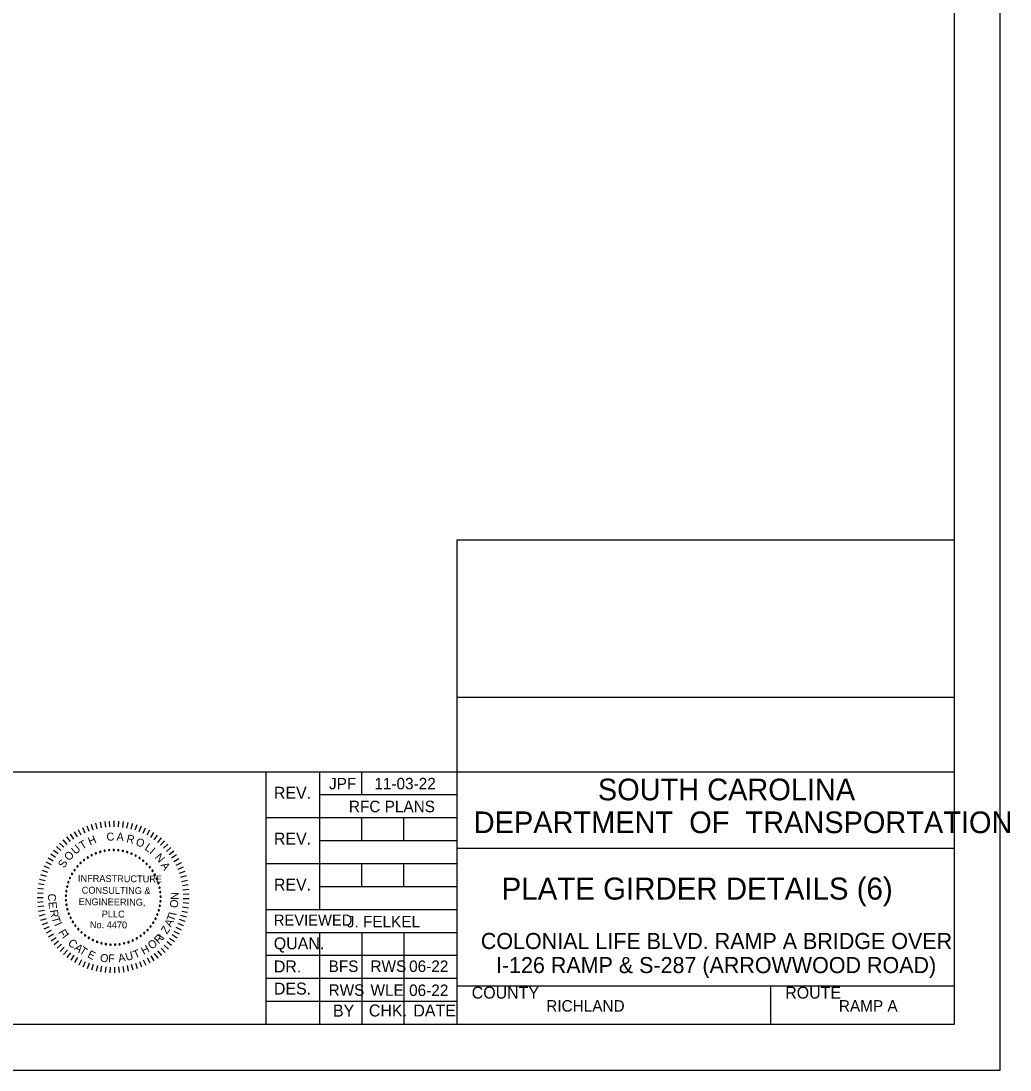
# Model space of a CAD drawing. Extents: x -383 to -161, y -356 to -94.
# Drawn here: x -203.87 to -160.75, y -187.49 to -141.77 of the extents above; entities that cross this region are included whole.
import ezdxf

# ---------------------------------------------------------------- set-up
doc = ezdxf.new("R2010")
doc.units = 0
for name, color, linetype in [('BR_BORDER LINES', 7, 'Continuous'), ('BR_TEXT', 7, 'Continuous'), ('Level 31', 7, 'Continuous')]:
    doc.layers.add(name, color=color, linetype=linetype)

msp = doc.modelspace()

# ---------------------------------------------------------------- linework, layer by layer
at = {"layer": 'BR_BORDER LINES'}
for p, q in [((-163.178, -185.489), (-163.178, -101.489)), ((-184.846, -185.489), (-184.846, -164.383)), ((-184.846, -164.383), (-163.178, -164.383)), ((-184.845, -171.242), (-163.178, -171.242)), ((-214.64, -174.489), (-193.18, -174.489)), ((-193.18, -185.489), (-193.18, -174.489)), ((-193.18, -174.489), (-163.178, -174.489)), ((-190.846, -174.489), (-190.846, -180.489)), ((-189.013, -175.489), (-189.013, -174.489)), ((-190.846, -175.489), (-184.846, -175.489)), ((-193.18, -176.489), (-184.846, -176.489)), ((-189.013, -177.489), (-189.013, -176.489)), ((-187.179, -177.489), (-187.179, -176.489)), ((-190.846, -177.489), (-184.846, -177.489)), ((-184.846, -177.822), (-184.846, -177.822)), ((-184.846, -177.823), (-163.178, -177.823)), ((-193.18, -178.489), (-184.846, -178.489)), ((-189.013, -179.489), (-189.013, -178.489)), ((-187.179, -179.489), (-187.179, -178.489)), ((-190.846, -179.489), (-184.846, -179.489)), ((-193.18, -180.489), (-184.846, -180.489)), ((-193.18, -181.489), (-184.846, -181.489)), ((-190.846, -181.489), (-190.846, -185.489)), ((-189.013, -181.489), (-189.013, -185.489)), ((-187.179, -181.489), (-187.179, -185.489)), ((-193.18, -182.489), (-184.846, -182.489)), ((-193.18, -183.489), (-184.846, -183.489)), ((-184.846, -183.823), (-163.178, -183.823)), ((-184.456, -183.823), (-163.178, -183.823)), ((-171.179, -185.489), (-171.179, -183.823)), ((-193.18, -184.489), (-184.846, -184.489)), ((-297.843, -185.489), (-163.178, -185.489))]:
    msp.add_line(p, q, dxfattribs=at)
at = {"layer": 'BR_TEXT'}
for p, q in [((-201.188, -176.92), (-201.084, -177.153)), ((-201.001, -176.844), (-200.912, -177.082)), ((-200.81, -176.779), (-200.735, -177.023)), ((-200.615, -176.726), (-200.555, -176.974)), ((-200.417, -176.685), (-200.373, -176.936)), ((-200.217, -176.656), (-200.188, -176.909)), ((-200.016, -176.64), (-200.002, -176.894)), ((-199.814, -176.636), (-199.816, -176.89)), ((-199.612, -176.644), (-199.63, -176.898)), ((-199.411, -176.664), (-199.444, -176.917)), ((-199.212, -176.697), (-199.26, -176.947)), ((-199.015, -176.741), (-199.079, -176.988)), ((-198.821, -176.798), (-198.9, -177.04)), ((-198.631, -176.866), (-198.724, -177.103)), ((-201.879, -177.334), (-201.723, -177.535)), ((-201.716, -177.215), (-201.572, -177.425)), ((-201.546, -177.106), (-201.415, -177.324)), ((-201.37, -177.007), (-201.252, -177.233)), ((-198.446, -176.946), (-198.553, -177.177)), ((-198.265, -177.037), (-198.387, -177.261)), ((-198.091, -177.139), (-198.226, -177.355)), ((-197.923, -177.251), (-198.071, -177.458)), ((-197.762, -177.373), (-197.922, -177.571)), ((-202.321, -177.748), (-202.13, -177.917)), ((-202.182, -177.601), (-202.002, -177.781)), ((-202.035, -177.463), (-201.866, -177.654)), ((-197.609, -177.505), (-197.781, -177.693)), ((-197.464, -177.646), (-197.647, -177.823)), ((-197.329, -177.795), (-197.522, -177.961)), ((-202.679, -178.235), (-202.461, -178.366)), ((-202.57, -178.065), (-202.36, -178.21)), ((-202.45, -177.903), (-202.25, -178.06)), ((-197.202, -177.952), (-197.405, -178.106)), ((-197.086, -178.117), (-197.298, -178.258)), ((-196.979, -178.289), (-197.199, -178.417)), ((-202.867, -178.593), (-202.634, -178.696)), ((-202.779, -178.411), (-202.553, -178.529)), ((-196.883, -178.467), (-197.111, -178.581)), ((-196.799, -178.65), (-197.033, -178.75)), ((-203.063, -179.165), (-202.815, -179.225)), ((-203.009, -178.97), (-202.766, -179.045)), ((-202.944, -178.779), (-202.705, -178.869)), ((-196.725, -178.838), (-196.965, -178.924)), ((-196.664, -179.03), (-196.908, -179.101)), ((-203.134, -179.562), (-202.881, -179.592)), ((-203.104, -179.363), (-202.853, -179.407)), ((-196.614, -179.226), (-196.862, -179.282)), ((-196.576, -179.424), (-196.827, -179.465)), ((-196.55, -179.625), (-196.804, -179.65)), ((-203.156, -179.965), (-202.901, -179.964)), ((-203.151, -179.764), (-202.897, -179.777)), ((-196.537, -179.826), (-196.791, -179.836)), ((-196.535, -180.028), (-196.79, -180.022)), ((-203.149, -180.167), (-202.895, -180.15)), ((-203.129, -180.368), (-202.877, -180.335)), ((-203.097, -180.568), (-202.847, -180.52)), ((-196.606, -180.629), (-196.855, -180.577)), ((-196.57, -180.43), (-196.822, -180.393)), ((-196.547, -180.23), (-196.8, -180.208)), ((-203.053, -180.765), (-202.807, -180.701)), ((-202.997, -180.959), (-202.755, -180.881)), ((-196.713, -181.018), (-196.954, -180.936)), ((-196.653, -180.825), (-196.899, -180.758)), ((-202.93, -181.149), (-202.693, -181.056)), ((-202.851, -181.335), (-202.62, -181.228)), ((-202.761, -181.516), (-202.536, -181.395)), ((-196.96, -181.57), (-197.182, -181.446)), ((-196.867, -181.392), (-197.096, -181.281)), ((-196.784, -181.207), (-197.02, -181.111)), ((-202.66, -181.69), (-202.443, -181.556)), ((-202.548, -181.859), (-202.34, -181.711)), ((-202.426, -182.02), (-202.228, -181.86)), ((-197.304, -182.068), (-197.5, -181.905)), ((-197.179, -181.91), (-197.385, -181.759)), ((-197.065, -181.743), (-197.279, -181.605)), ((-202.295, -182.173), (-202.107, -182.002)), ((-202.155, -182.319), (-201.977, -182.136)), ((-202.006, -182.455), (-201.84, -182.262)), ((-201.849, -182.582), (-201.695, -182.379)), ((-197.733, -182.495), (-197.895, -182.3)), ((-197.581, -182.362), (-197.756, -182.176)), ((-197.438, -182.219), (-197.623, -182.045)), ((-201.685, -182.699), (-201.543, -182.487)), ((-201.513, -182.806), (-201.385, -182.586)), ((-201.336, -182.903), (-201.221, -182.675)), ((-201.153, -182.988), (-201.053, -182.754)), ((-200.965, -183.062), (-200.879, -182.822)), ((-198.785, -183.083), (-198.867, -182.842)), ((-198.596, -183.012), (-198.692, -182.777)), ((-198.411, -182.93), (-198.522, -182.701)), ((-198.232, -182.837), (-198.356, -182.615)), ((-198.059, -182.734), (-198.196, -182.519)), ((-197.892, -182.62), (-198.042, -182.414)), ((-200.773, -183.125), (-200.702, -182.88)), ((-200.577, -183.175), (-200.521, -182.927)), ((-200.379, -183.214), (-200.338, -182.962)), ((-200.179, -183.24), (-200.154, -182.987)), ((-199.978, -183.254), (-199.968, -183)), ((-199.776, -183.256), (-199.781, -183.002)), ((-199.574, -183.246), (-199.595, -182.992)), ((-199.373, -183.223), (-199.41, -182.971)), ((-199.174, -183.188), (-199.226, -182.939)), ((-198.978, -183.142), (-199.045, -182.896))]:
    msp.add_line(p, q, dxfattribs=at)
for centre, start, end in [((-200.957, -178.226), 32.7576, 212.7576), ((-200.957, -178.226), 212.7576, 32.7576), ((-200.785, -178.127), 27.2191, 207.2191), ((-200.785, -178.127), 207.2191, 27.2191), ((-200.603, -178.045), 21.6807, 201.6807), ((-200.603, -178.045), 201.6807, 21.6807), ((-200.414, -177.98), 16.1422, 196.1422), ((-200.414, -177.98), 196.1422, 16.1422), ((-200.22, -177.935), 10.6038, 190.6038), ((-200.22, -177.935), 190.6038, 10.6038), ((-200.023, -177.908), 5.0653, 185.0653), ((-200.023, -177.908), 185.0653, 5.0653), ((-199.824, -177.9), 359.5268, 179.5268), ((-199.824, -177.9), 179.5268, 359.5268), ((-199.625, -177.912), 353.9884, 173.9884), ((-199.625, -177.912), 173.9884, 353.9884), ((-199.428, -177.943), 168.4499, 348.4499), ((-199.428, -177.943), 348.4499, 168.4499), ((-199.235, -177.992), 162.9114, 342.9114), ((-199.235, -177.992), 342.9114, 162.9114), ((-199.047, -178.06), 157.373, 337.373), ((-199.047, -178.06), 337.373, 157.373), ((-198.867, -178.146), 151.8345, 331.8345), ((-198.867, -178.146), 331.8345, 151.8345), ((-198.697, -178.249), 146.2961, 326.2961), ((-198.697, -178.249), 326.2961, 146.2961), ((-201.53, -178.774), 54.9114, 234.9114), ((-201.53, -178.774), 234.9114, 54.9114), ((-201.408, -178.617), 49.373, 229.373), ((-201.408, -178.617), 229.373, 49.373), ((-201.27, -178.472), 43.8345, 223.8345), ((-201.27, -178.472), 223.8345, 43.8345), ((-201.12, -178.341), 38.2961, 218.2961), ((-201.12, -178.341), 218.2961, 38.2961), ((-198.537, -178.368), 140.7576, 320.7576), ((-198.537, -178.368), 320.7576, 140.7576), ((-198.389, -178.502), 135.2191, 315.2191), ((-198.389, -178.502), 315.2191, 135.2191), ((-198.255, -178.649), 129.6807, 309.6807), ((-198.255, -178.649), 309.6807, 129.6807), ((-201.727, -179.12), 65.9884, 245.9884), ((-201.727, -179.12), 245.9884, 65.9884), ((-201.637, -178.942), 60.4499, 240.4499), ((-201.637, -178.942), 240.4499, 60.4499), ((-198.135, -178.809), 124.1422, 304.1422), ((-198.135, -178.809), 304.1422, 124.1422), ((-198.032, -178.979), 118.6038, 298.6038), ((-198.032, -178.979), 298.6038, 118.6038), ((-197.945, -179.159), 113.0653, 293.0653), ((-197.945, -179.159), 293.0653, 113.0653), ((-201.89, -179.693), 82.6038, 262.6038), ((-201.89, -179.693), 262.6038, 82.6038), ((-201.854, -179.497), 77.0653, 257.0653), ((-201.854, -179.497), 257.0653, 77.0653), ((-201.8, -179.305), 71.5268, 251.5268), ((-201.8, -179.305), 251.5268, 71.5268), ((-197.876, -179.346), 107.5268, 287.5268), ((-197.876, -179.346), 287.5268, 107.5268), ((-197.826, -179.538), 101.9884, 281.9884), ((-197.826, -179.538), 281.9884, 101.9884), ((-201.906, -179.892), 88.1422, 268.1422), ((-201.904, -180.091), 93.6807, 273.6807), ((-201.906, -179.892), 268.1422, 88.1422), ((-201.904, -180.091), 273.6807, 93.6807), ((-197.795, -179.735), 96.4499, 276.4499), ((-197.789, -180.133), 85.373, 265.373), ((-197.782, -179.934), 90.9114, 270.9114), ((-197.795, -179.735), 276.4499, 96.4499), ((-197.789, -180.133), 265.373, 85.373), ((-197.782, -179.934), 270.9114, 90.9114), ((-201.882, -180.289), 99.2191, 279.2191), ((-201.882, -180.289), 279.2191, 99.2191), ((-201.841, -180.484), 104.7576, 284.7576), ((-201.841, -180.484), 284.7576, 104.7576), ((-197.86, -180.525), 74.2961, 254.2961), ((-197.86, -180.525), 254.2961, 74.2961), ((-197.815, -180.331), 79.8345, 259.8345), ((-197.815, -180.331), 259.8345, 79.8345), ((-201.781, -180.675), 110.2961, 290.2961), ((-201.781, -180.675), 290.2961, 110.2961), ((-201.703, -180.858), 115.8345, 295.8345), ((-201.703, -180.858), 295.8345, 115.8345), ((-201.608, -181.033), 121.373, 301.373), ((-201.608, -181.033), 301.373, 121.373), ((-198.005, -180.896), 63.2191, 243.2191), ((-198.005, -180.896), 243.2191, 63.2191), ((-197.924, -180.714), 68.7576, 248.7576), ((-197.924, -180.714), 248.7576, 68.7576), ((-201.497, -181.199), 126.9114, 306.9114), ((-201.497, -181.199), 306.9114, 126.9114), ((-201.37, -181.352), 132.4499, 312.4499), ((-201.37, -181.352), 312.4499, 132.4499), ((-201.228, -181.493), 137.9884, 317.9884), ((-201.228, -181.493), 317.9884, 137.9884), ((-198.493, -181.521), 41.0653, 221.0653), ((-198.349, -181.383), 46.6038, 226.6038), ((-198.349, -181.383), 226.6038, 46.6038), ((-198.219, -181.232), 52.1422, 232.1422), ((-198.219, -181.232), 232.1422, 52.1422), ((-198.104, -181.069), 57.6807, 237.6807), ((-198.104, -181.069), 237.6807, 57.6807), ((-201.074, -181.619), 143.5268, 323.5268), ((-201.074, -181.619), 323.5268, 143.5268), ((-200.909, -181.73), 149.0653, 329.0653), ((-200.909, -181.73), 329.0653, 149.0653), ((-200.733, -181.825), 154.6038, 334.6038), ((-200.733, -181.825), 334.6038, 154.6038), ((-200.549, -181.902), 160.1422, 340.1422), ((-200.549, -181.902), 340.1422, 160.1422), ((-200.359, -181.961), 345.6807, 165.6807), ((-199.372, -181.971), 13.373, 193.373), ((-199.18, -181.916), 18.9114, 198.9114), ((-199.18, -181.916), 198.9114, 18.9114), ((-198.995, -181.842), 24.4499, 204.4499), ((-198.995, -181.842), 204.4499, 24.4499), ((-198.817, -181.752), 29.9884, 209.9884), ((-198.817, -181.752), 209.9884, 29.9884), ((-198.649, -181.644), 35.5268, 215.5268), ((-198.649, -181.644), 215.5268, 35.5268), ((-198.493, -181.521), 221.0653, 41.0653), ((-200.359, -181.961), 165.6807, 345.6807), ((-200.164, -182.001), 171.2191, 351.2191), ((-200.164, -182.001), 351.2191, 171.2191), ((-199.965, -182.022), 176.7576, 356.7576), ((-199.965, -182.022), 356.7576, 176.7576), ((-199.766, -182.024), 2.2961, 182.2961), ((-199.766, -182.024), 182.2961, 2.2961), ((-199.568, -182.007), 7.8345, 187.8345), ((-199.568, -182.007), 187.8345, 7.8345), ((-199.372, -181.971), 193.373, 13.373)]:
    msp.add_arc(centre, 0.028, start, end, dxfattribs=at)
at = {"layer": 'Level 31'}
msp.add_line((-174.011, -179.583), (-174.011, -179.583), dxfattribs=at)
msp.add_lwpolyline([(-305.176, -187.489), (-161.176, -187.489), (-161.176, -99.489), (-305.176, -99.489)], close=True, dxfattribs=at)

# ---------------------------------------------------------------- texts
at = {"layer": 'BR_TEXT'}
for s, height, p in [('JPF', 0.5, (-190.438, -175.257)), ('11-03-22', 0.5, (-188.461, -175.257)), ('SOUTH CAROLINA', 0.94348, (-178.718, -175.735)), ('REV.', 0.52, (-192.841, -175.667)), ('RFC PLANS', 0.5, (-189.572, -176.253)), ('DEPARTMENT  OF  TRANSPORTATION', 0.94348, (-184.129, -177.166)), ('REV.', 0.52, (-192.841, -177.667)), ('REV.', 0.52, (-192.841, -179.667)), ('PLATE GIRDER DETAILS (6)', 0.96, (-182.913, -180.063)), ('REVIEWED', 0.48, (-192.843, -181.195)), ('J. FELKEL', 0.5, (-189.664, -181.272)), ('QUAN.', 0.52, (-192.846, -182.229)), ('COLONIAL LIFE BLVD. RAMP A BRIDGE OVER', 0.7, (-183.82, -182.216)), ('DR.', 0.52, (-192.845, -183.235)), ('BFS', 0.5, (-190.457, -183.215)), ('RWS', 0.5, (-188.632, -183.215)), ('06-22', 0.5, (-186.946, -183.215)), ('I-126 RAMP & S-287 (ARROWWOOD ROAD)', 0.7, (-183.162, -183.266)), ('DES.', 0.52, (-192.841, -184.2)), ('RWS', 0.5, (-190.457, -184.254)), ('WLE', 0.5, (-188.63, -184.254)), ('06-22', 0.5, (-186.946, -184.263)), ('COUNTY', 0.52, (-184.217, -184.376)), ('ROUTE', 0.52, (-170.55, -184.376)), ('BY', 0.52, (-190.265, -185.161)), ('CHK.', 0.52, (-188.701, -185.156)), ('DATE', 0.52, (-186.761, -185.156)), ('RICHLAND', 0.5, (-180.968, -184.944)), ('RAMP A', 0.5, (-168.212, -184.944))]:
    msp.add_text(s, height=height, dxfattribs=at).set_placement(p)
for s, height, rotation, p in [('H', 0.349, 22.7882, (-200.857, -177.704)), ('C', 0.349, 4.7281, (-200.126, -177.506)), ('A', 0.349, 355.6981, (-199.708, -177.486)), ('R', 0.349, 346.6681, (-199.291, -177.554)), ('U', 0.349, 40.8482, (-201.49, -178.119)), ('T', 0.349, 31.8182, (-201.196, -177.894)), ('O', 0.349, 337.638, (-198.9, -177.673)), ('L', 0.349, 327.108, (-198.504, -177.875)), ('I', 0.349, 319.578, (-198.294, -178.026)), ('O', 0.349, 49.8782, (-201.757, -178.403)), ('N', 0.349, 310.548, (-198.051, -178.23)), ('S', 0.349, 58.9083, (-201.979, -178.715)), ('A', 0.349, 301.5179, (-197.791, -178.559)), ('INFRASTRUCTURE', 0.29909, 359.5268, (-201.385, -179.286)), ('CONSULTING &', 0.29909, 359.5268, (-201.22, -179.8)), ('C', 0.349, 267.025, (-202.679, -179.795)), ('ENGINEERING,', 0.29909, 359.5268, (-201.354, -180.302)), ('O', 0.349, 83.2085, (-197.038, -180.44)), ('N', 0.349, 89.2085, (-196.993, -180.074)), ('E', 0.349, 273.025, (-202.662, -180.161)), ('R', 0.349, 279.025, (-202.61, -180.531)), ('PLLC', 0.2991, 359.5268, (-200.347, -180.836)), ('T', 0.349, 285.025, (-202.541, -180.846)), ('I', 0.349, 293.7713, (-202.422, -181.138)), ('No. 4470', 0.2991, 359.5268, (-200.865, -181.304)), ('A', 0.349, 63.3954, (-197.326, -181.288)), ('T', 0.349, 69.3954, (-197.203, -181.047)), ('I', 0.349, 77.9093, (-197.1, -180.777)), ('F', 0.349, 299.7713, (-202.257, -181.482)), ('Z', 0.349, 57.3954, (-197.501, -181.594)), ('I', 0.349, 308.5268, (-202.089, -181.698)), ('C', 0.349, 314.5268, (-201.851, -181.978)), ('O', 0.349, 38.5268, (-198.169, -182.254)), ('R', 0.349, 44.5268, (-197.863, -182.014)), ('I', 0.349, 52.3339, (-197.665, -181.825)), ('A', 0.349, 320.5268, (-201.575, -182.213)), ('T', 0.349, 326.5268, (-201.357, -182.366)), ('E', 0.349, 332.5268, (-201.003, -182.558)), ('U', 0.349, 16.5268, (-199.261, -182.742)), ('T', 0.349, 22.5268, (-198.894, -182.645)), ('H', 0.349, 28.5268, (-198.522, -182.478)), ('O', 0.349, 350.5268, (-200.442, -182.753)), ('F', 0.349, 356.5268, (-200.076, -182.79)), ('A', 0.349, 10.5268, (-199.597, -182.796))]:
    msp.add_text(s, height=height, rotation=rotation, dxfattribs=at).set_placement(p)

doc.saveas('drawing.dxf')
